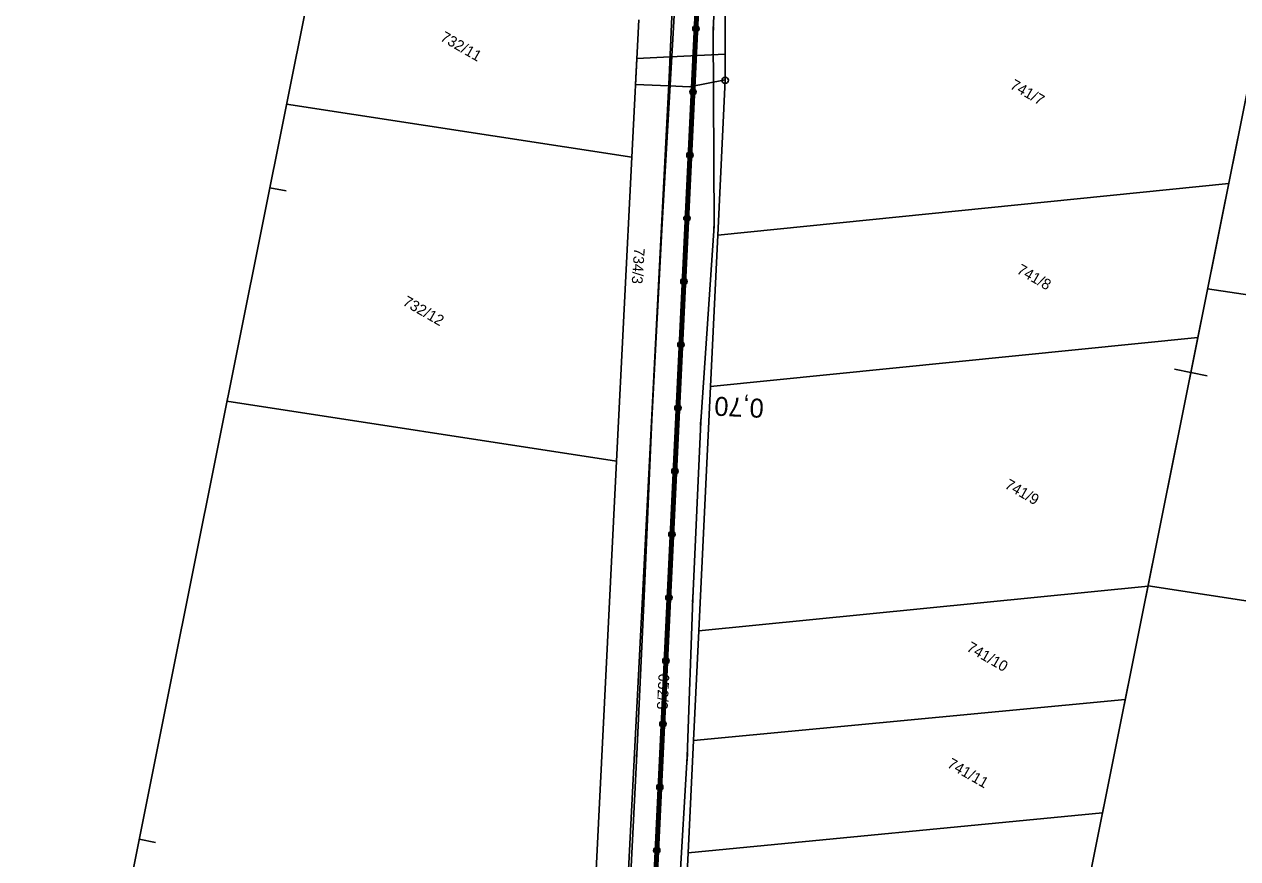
# Model space of a CAD drawing. Extents: x -548552 to -543113, y -1131925 to -1123599.
# Drawn here: x -548371.9 to -548180.1, y -1131173.6 to -1131041.8 of the extents above; entities that cross this region are included whole.
import ezdxf

# ---------------------------------------------------------------- set-up
doc = ezdxf.new("R2010")
doc.units = 0
for name, color, linetype in [('Hranice parcel', 7, 'Continuous'), ('Parcelní čísla', 7, 'Continuous'), ('Profile', 7, 'Continuous'), ('PROFILY NÁVRH', 7, 'Continuous'), ('STANIČENÍ', 7, 'Continuous'), ('Věcná břemena k části', 7, 'Continuous'), ('Značky bodu BP', 7, 'Continuous')]:
    doc.layers.add(name, color=color, linetype=linetype)

msp = doc.modelspace()

# ---------------------------------------------------------------- linework, layer by layer
at = {"layer": 'Hranice parcel'}
for p, q in [((-548275.88, -1131062.79), (-548274.79, -1131041.06)), ((-548330.48, -1131054.37), (-548275.88, -1131062.79)), ((-548278.29, -1131110.83), (-548275.88, -1131062.79)), ((-548262.3, -1131075.09), (-548181.54, -1131066.91)), ((-548263.45, -1131099.02), (-548262.3, -1131075.09)), ((-548184.87, -1131083.55), (-548130.28, -1131091.97)), ((-548263.45, -1131099.02), (-548186.42, -1131091.26)), ((-548265.3, -1131137.62), (-548263.45, -1131099.02)), ((-548278.29, -1131110.83), (-548339.89, -1131101.33)), ((-548265.3, -1131137.62), (-548194.29, -1131130.55)), ((-548132.68, -1131140.02), (-548194.29, -1131130.51)), ((-548266.14, -1131154.93), (-548265.3, -1131137.62)), ((-548266.14, -1131154.93), (-548197.89, -1131148.49)), ((-548266.99, -1131172.73), (-548266.14, -1131154.93)), ((-548201.48, -1131166.4), (-548266.99, -1131172.73)), ((-548268.63, -1131206.89), (-548266.99, -1131172.73))]:
    msp.add_line(p, q, dxfattribs=at)
for points in [[(-548264.85, -1130945.08), (-548269.14, -1131030.91), (-548269.98, -1131050.17), (-548279.48, -1131235), (-548279.89, -1131244)], [(-548262.3, -1131075.09), (-548261.13, -1131050.62), (-548261.12, -1131036.32)], [(-548284.67, -1131243.76), (-548284.5, -1131234.77), (-548278.29, -1131110.83)]]:
    msp.add_lwpolyline(points, dxfattribs=at)
at = {"layer": 'Profile'}
for p, q in [((-548309.46, -1130949.53), (-548348.82, -1131145.88)), ((-548163.86, -1130978.72), (-548203.22, -1131175.07)), ((-548325.71, -1131030.6), (-548348.82, -1131145.88)), ((-548180.11, -1131059.78), (-548203.22, -1131175.07)), ((-548180.11, -1131059.78), (-548203.22, -1131175.07)), ((-548330.54, -1131068.11), (-548333.13, -1131067.59)), ((-548187.52, -1131096.78), (-548190.11, -1131096.26)), ((-548184.93, -1131097.3), (-548187.52, -1131096.78)), ((-548348.82, -1131145.88), (-548371.93, -1131261.16)), ((-548348.82, -1131145.88), (-548371.93, -1131261.16)), ((-548351.17, -1131171.06), (-548353.76, -1131170.54))]:
    msp.add_line(p, q, dxfattribs=at)
at = {"layer": 'PROFILY NÁVRH'}
for p, q in [((-548276, -1131252.52), (-548261.4, -1130945.78)), ((-548275.5, -1131252.55), (-548260.91, -1130945.87)), ((-548267.33, -1131003.3), (-548269.29, -1131042.28)), ((-548261.25, -1131003.59), (-548263.02, -1131042.58)), ((-548269.29, -1131042.28), (-548271.1, -1131073.23)), ((-548263.02, -1131042.58), (-548262.87, -1131073.62)), ((-548271.1, -1131073.23), (-548272.75, -1131104.23)), ((-548262.87, -1131073.62), (-548265, -1131104.6)), ((-548272.75, -1131104.23), (-548273.95, -1131132.17)), ((-548265, -1131104.6), (-548266.26, -1131132.54)), ((-548273.95, -1131132.17), (-548275.11, -1131157.13)), ((-548266.26, -1131132.54), (-548267.13, -1131157.51)), ((-548275.11, -1131157.13), (-548276.81, -1131192.09)), ((-548267.13, -1131157.51), (-548269.17, -1131192.46))]:
    msp.add_line(p, q, dxfattribs=at)
at = {"layer": 'STANIČENÍ'}
for p, q in [((-548275.75, -1131252.54), (-548261.16, -1130945.83)), ((-548269.3, -1131042.55), (-548269.28, -1131041.99)), ((-548263.05, -1131043.33), (-548263, -1131042.15)), ((-548271.11, -1131073.42), (-548271.1, -1131073.14)), ((-548262.9, -1131074.1), (-548262.86, -1131073.26)), ((-548265.02, -1131105.11), (-548264.97, -1131104.1)), ((-548273.97, -1131132.52), (-548273.93, -1131131.88)), ((-548266.28, -1131133.1), (-548266.2, -1131131.41)), ((-548275.13, -1131157.61), (-548275.09, -1131156.76)), ((-548267.16, -1131158.16), (-548267.09, -1131156.85))]:
    msp.add_line(p, q, dxfattribs=at)
for centre, radius in [((-548265.76, -1131042.47), 0.5), ((-548265.8, -1131043.44), 0.1), ((-548265.75, -1131042.44), 0.1), ((-548265.9, -1131045.44), 0.1), ((-548265.85, -1131044.44), 0.1), ((-548265.99, -1131047.44), 0.1), ((-548265.94, -1131046.44), 0.1), ((-548266.09, -1131049.44), 0.1), ((-548266.04, -1131048.44), 0.1), ((-548266.18, -1131051.43), 0.1), ((-548266.14, -1131050.44), 0.1), ((-548266.23, -1131052.46), 0.5), ((-548266.28, -1131053.43), 0.1), ((-548266.23, -1131052.43), 0.1), ((-548266.37, -1131055.43), 0.1), ((-548266.33, -1131054.43), 0.1), ((-548266.47, -1131057.43), 0.1), ((-548266.42, -1131056.43), 0.1), ((-548266.56, -1131059.43), 0.1), ((-548266.52, -1131058.43), 0.1), ((-548266.66, -1131061.42), 0.1), ((-548266.61, -1131060.43), 0.1), ((-548266.71, -1131062.45), 0.5), ((-548266.71, -1131062.42), 0.1), ((-548266.8, -1131064.42), 0.1), ((-548266.75, -1131063.42), 0.1), ((-548266.9, -1131066.42), 0.1), ((-548266.85, -1131065.42), 0.1), ((-548266.99, -1131068.42), 0.1), ((-548266.94, -1131067.42), 0.1), ((-548267.09, -1131070.41), 0.1), ((-548267.04, -1131069.42), 0.1), ((-548267.18, -1131072.43), 0.5), ((-548267.18, -1131072.41), 0.1), ((-548267.13, -1131071.41), 0.1), ((-548267.28, -1131074.41), 0.1), ((-548267.23, -1131073.41), 0.1), ((-548267.37, -1131076.41), 0.1), ((-548267.32, -1131075.41), 0.1), ((-548267.47, -1131078.41), 0.1), ((-548267.42, -1131077.41), 0.1), ((-548267.56, -1131080.4), 0.1), ((-548267.51, -1131079.4), 0.1), ((-548267.66, -1131082.42), 0.5), ((-548267.66, -1131082.4), 0.1), ((-548267.61, -1131081.4), 0.1), ((-548267.75, -1131084.4), 0.1), ((-548267.7, -1131083.4), 0.1), ((-548267.8, -1131085.4), 0.1), ((-548267.89, -1131087.4), 0.1), ((-548267.89, -1131087.42), 0.1), ((-548267.85, -1131086.4), 0.1), ((-548267.99, -1131089.39), 0.1), ((-548267.94, -1131088.39), 0.1), ((-548267.94, -1131088.42), 0.1), ((-548268.13, -1131092.41), 0.5), ((-548268.08, -1131091.39), 0.1), ((-548268.04, -1131090.39), 0.1), ((-548268.18, -1131093.39), 0.1), ((-548268.13, -1131092.39), 0.1), ((-548268.27, -1131095.39), 0.1), ((-548268.23, -1131094.39), 0.1), ((-548268.37, -1131097.39), 0.1), ((-548268.32, -1131096.39), 0.1), ((-548268.46, -1131099.38), 0.1), ((-548268.42, -1131098.38), 0.1), ((-548268.56, -1131101.38), 0.1), ((-548268.51, -1131100.38), 0.1), ((-548268.61, -1131102.4), 0.5), ((-548268.65, -1131103.38), 0.1), ((-548268.61, -1131102.38), 0.1), ((-548268.75, -1131105.38), 0.1), ((-548268.7, -1131104.38), 0.1), ((-548268.84, -1131107.37), 0.1), ((-548268.8, -1131106.38), 0.1), ((-548268.94, -1131109.37), 0.1), ((-548268.89, -1131108.37), 0.1), ((-548268.99, -1131110.37), 0.1), ((-548269.08, -1131112.39), 0.5), ((-548269.08, -1131112.37), 0.1), ((-548269.03, -1131111.37), 0.1), ((-548269.18, -1131114.37), 0.1), ((-548269.13, -1131113.37), 0.1), ((-548269.27, -1131116.36), 0.1), ((-548269.22, -1131115.37), 0.1), ((-548269.37, -1131118.36), 0.1), ((-548269.32, -1131117.36), 0.1), ((-548269.46, -1131120.36), 0.1), ((-548269.41, -1131119.36), 0.1), ((-548269.56, -1131122.38), 0.5), ((-548269.56, -1131122.36), 0.1), ((-548269.51, -1131121.36), 0.1), ((-548269.65, -1131124.36), 0.1), ((-548269.61, -1131123.36), 0.1), ((-548269.75, -1131126.35), 0.1), ((-548269.7, -1131125.36), 0.1), ((-548269.84, -1131128.35), 0.1), ((-548269.8, -1131127.35), 0.1), ((-548269.94, -1131130.35), 0.1), ((-548269.89, -1131129.35), 0.1), ((-548270.03, -1131132.37), 0.5), ((-548270.03, -1131132.35), 0.1), ((-548269.99, -1131131.35), 0.1), ((-548270.13, -1131134.35), 0.1), ((-548270.08, -1131133.35), 0.1), ((-548270.18, -1131135.34), 0.1), ((-548270.27, -1131137.34), 0.1), ((-548270.22, -1131136.34), 0.1), ((-548270.37, -1131139.34), 0.1), ((-548270.32, -1131138.34), 0.1), ((-548270.51, -1131142.36), 0.5), ((-548270.46, -1131141.34), 0.1), ((-548270.41, -1131140.34), 0.1), ((-548270.56, -1131143.34), 0.1), ((-548270.51, -1131142.34), 0.1), ((-548270.65, -1131145.33), 0.1), ((-548270.6, -1131144.33), 0.1), ((-548270.75, -1131147.33), 0.1), ((-548270.7, -1131146.33), 0.1), ((-548270.84, -1131149.33), 0.1), ((-548270.79, -1131148.33), 0.1), ((-548270.94, -1131151.33), 0.1), ((-548270.89, -1131150.33), 0.1), ((-548270.98, -1131152.34), 0.5), ((-548271.03, -1131153.32), 0.1), ((-548270.98, -1131152.33), 0.1), ((-548271.13, -1131155.32), 0.1), ((-548271.08, -1131154.32), 0.1), ((-548271.22, -1131157.32), 0.1), ((-548271.17, -1131156.32), 0.1), ((-548271.27, -1131158.32), 0.1), ((-548271.36, -1131160.32), 0.1), ((-548271.32, -1131159.32), 0.1), ((-548271.46, -1131162.33), 0.5), ((-548271.46, -1131162.32), 0.1), ((-548271.41, -1131161.32), 0.1), ((-548271.55, -1131164.31), 0.1), ((-548271.51, -1131163.31), 0.1), ((-548271.65, -1131166.31), 0.1), ((-548271.6, -1131165.31), 0.1), ((-548271.74, -1131168.31), 0.1), ((-548271.7, -1131167.31), 0.1), ((-548271.84, -1131170.31), 0.1), ((-548271.79, -1131169.31), 0.1), ((-548271.94, -1131172.32), 0.5), ((-548271.93, -1131172.3), 0.1), ((-548271.89, -1131171.31), 0.1), ((-548271.98, -1131173.3), 0.1)]:
    msp.add_circle(centre, radius, dxfattribs=at)
at = {"layer": 'Věcná břemena k části'}
for points in [[(-548270.05, -1131051.5), (-548269.84, -1131046.92), (-548275.1, -1131047.19), (-548275.3, -1131051.28)], [(-548270.05, -1131051.5), (-548269.84, -1131046.92), (-548275.1, -1131047.19), (-548275.3, -1131051.28)], [(-548269.84, -1131046.92), (-548270.05, -1131051.5), (-548266.79, -1131051.64), (-548261.13, -1131050.57), (-548261.12, -1131046.47)]]:
    msp.add_lwpolyline(points, close=True, dxfattribs=at)
at = {"layer": 'Značky bodu BP'}
for radius in [0.5, 0.0303]:
    msp.add_circle((-548261.13, -1131050.62), radius, dxfattribs=at)

# ---------------------------------------------------------------- texts
at = {"layer": 'Parcelní čísla'}
for s, rotation, p in [('732/11', 330.1814, (-548306.3, -1131044.26)), ('741/7', 330.1814, (-548216.23, -1131051.83)), ('734/3', 266.1814, (-548275.53, -1131077.07)), ('741/8', 330.1814, (-548215.17, -1131081.03)), ('732/12', 330.1814, (-548312.24, -1131086.06)), ('741/9', 330.1814, (-548217.08, -1131114.99)), ('741/10', 330.1814, (-548223.1, -1131140.71)), ('652/3', 267.1814, (-548271.65, -1131144.34)), ('741/11', 330.1814, (-548226.17, -1131159.1))]:
    msp.add_text(s, height=1.7, rotation=rotation, dxfattribs=at).set_placement(p)
at = {"layer": 'STANIČENÍ'}
msp.add_text('0,70', height=3, rotation=177.2755, dxfattribs=at).set_placement((-548254.96, -1131100.98))

doc.saveas('drawing.dxf')
